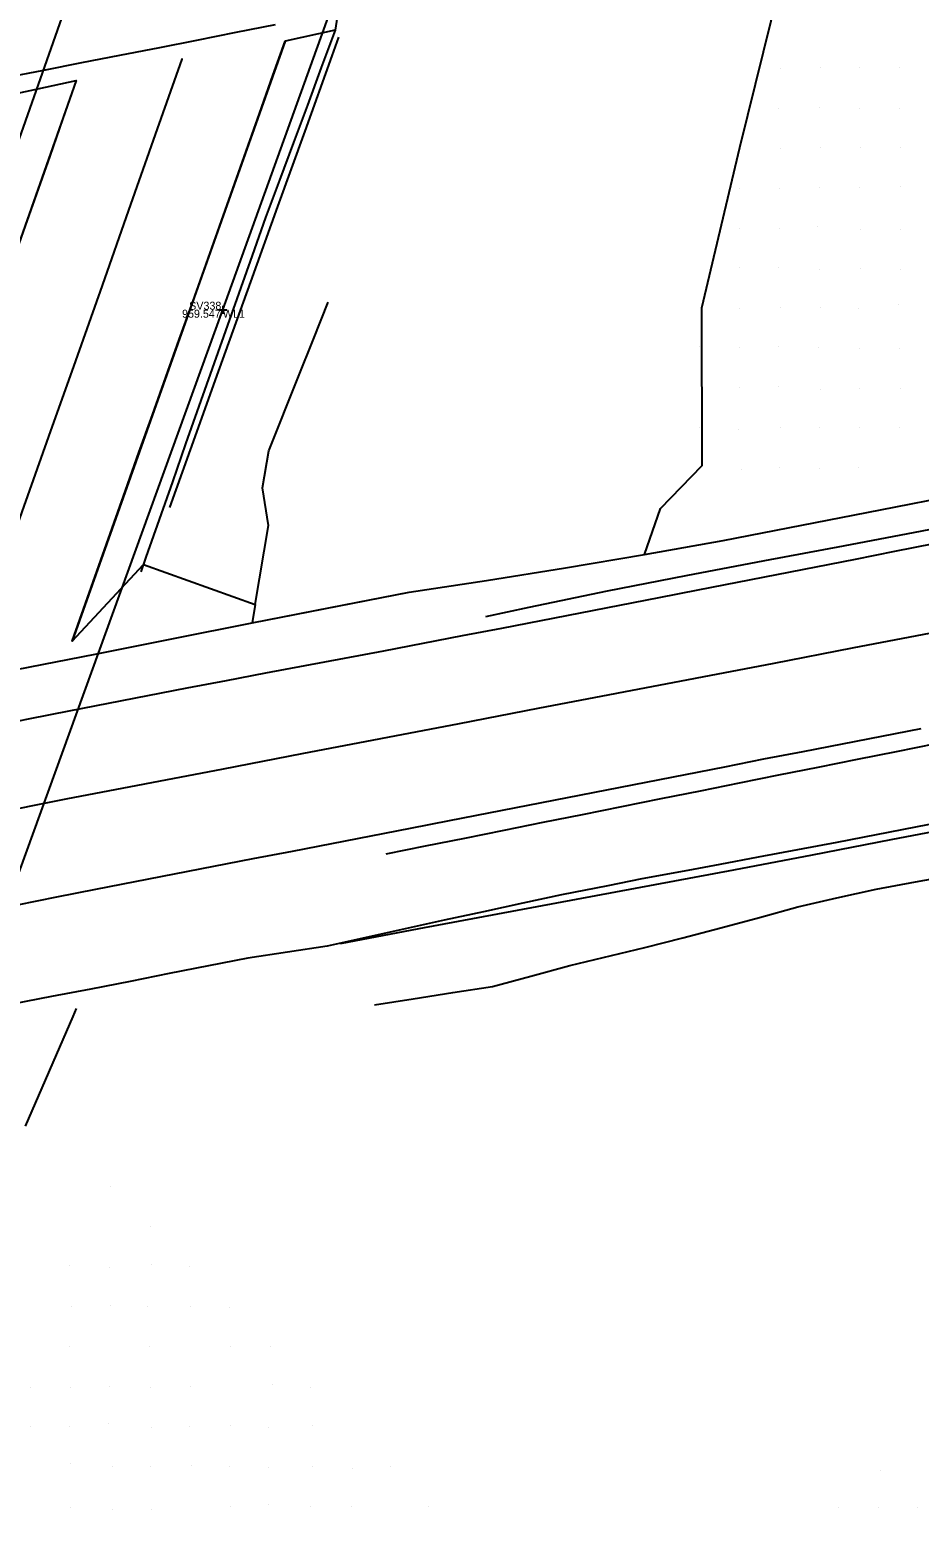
# Model space of a CAD drawing. Extents: x 2262025 to 2264532, y 740981 to 742724.
# Drawn here: x 2263228.5 to 2263339.6, y 741976.8 to 742163 of the extents above; entities that cross this region are included whole.
import ezdxf

# ---------------------------------------------------------------- set-up
doc = ezdxf.new("R2010")
doc.units = 0
for name, color, linetype in [('DT_X_Void', 7, 'Continuous'), ('GE_X_Alignment_1000_Curve_Data', 7, 'Continuous'), ('GE_X_Alignment_100_Bearings', 7, 'Continuous'), ('GE_X_Alignment_100_Curve_Data', 7, 'Continuous'), ('Ground Shots', 7, 'Continuous'), ('HY_X_Spring_Cells', 7, 'Continuous'), ('RW_X_CL', 7, 'Continuous'), ('RW_X_CL_1000_Distances', 7, 'Continuous'), ('RW_X_CL_100_Cardinal_Points', 7, 'Continuous'), ('SC_Scratch2', 7, 'Continuous'), ('SC_Scratch4', 7, 'Continuous'), ('SV_X_Control_Cells_Found', 7, 'Continuous'), ('SV_X_Text_Comment', 7, 'Continuous'), ('UT_X_Gas', 7, 'Continuous'), ('UT_X_Water', 7, 'Continuous')]:
    doc.layers.add(name, color=color, linetype=linetype)

msp = doc.modelspace()

# ---------------------------------------------------------------- linework, layer by layer
at = {"layer": 'DT_X_Void'}
for points in [[(2263307.26, 742103.15), (2263312.47, 742108.54), (2263312.43, 742128.22), (2263317.18, 742148.27), (2263322.09, 742168.18), (2263320.51, 742176.01), (2263266.96, 742165.11), (2263266.63, 742162.94), (2263260.36, 742161.57), (2263233.77, 742086.56), (2263242.67, 742096.15), (2263256.64, 742091.14), (2263256.25, 742088.84), (2263275.88, 742092.68), (2263285.52, 742094.16), (2263295.38, 742095.74), (2263305.24, 742097.38)], [(2263148.35, 742084.34), (2263148.83, 742139.39), (2263148.85, 742141.53), (2263177.37, 742146.41), (2263223.67, 742154.36), (2263228.51, 742155.39), (2263234.29, 742156.62), (2263207.86, 742081.52), (2263207.2, 742079.17), (2263202.2, 742080.57), (2263196.1, 742079.91), (2263195.53, 742076.88), (2263158.09, 742069.91), (2263148.41, 742067.47)]]:
    msp.add_lwpolyline(points, close=True, dxfattribs=at)
at = {"layer": 'GE_X_Alignment_1000_Curve_Data'}
for points in [[(2263457.67, 742123.27), (2263447.86, 742121.35), (2263438.05, 742119.42), (2263428.24, 742117.48), (2263418.43, 742115.54), (2263408.62, 742113.6), (2263398.81, 742111.66), (2263389, 742109.72), (2263379.19, 742107.78), (2263369.36, 742105.92), (2263359.54, 742104.05), (2263349.71, 742102.19), (2263339.89, 742100.32), (2263330.06, 742098.45), (2263320.24, 742096.59), (2263310.41, 742094.72), (2263300.59, 742092.83), (2263290.81, 742090.76), (2263285.41, 742089.61)], [(2263273.01, 742059.99), (2263277.92, 742060.98), (2263282.82, 742061.96), (2263287.72, 742062.95), (2263292.62, 742063.93), (2263297.52, 742064.92), (2263302.43, 742065.9), (2263307.33, 742066.89), (2263312.23, 742067.87), (2263317.13, 742068.85), (2263322.03, 742069.84), (2263326.94, 742070.82), (2263331.84, 742071.81), (2263336.74, 742072.79), (2263341.64, 742073.78)]]:
    msp.add_lwpolyline(points, dxfattribs=at)
at = {"layer": 'GE_X_Alignment_100_Bearings'}
for points in [[(2263245.96, 742103.26), (2263249.34, 742112.67), (2263251.69, 742119.21), (2263256.1, 742131.49), (2263259.48, 742140.9), (2263262.86, 742150.31), (2263266.25, 742159.72), (2263267.08, 742162.04)], [(2263267.27, 742048.8), (2263277.1, 742050.64), (2263286.93, 742052.48), (2263296.76, 742054.32), (2263306.59, 742056.16), (2263316.42, 742058), (2263326.24, 742059.88), (2263336.06, 742061.77), (2263345.88, 742063.65), (2263355.7, 742065.53), (2263365.53, 742067.41), (2263375.35, 742069.28), (2263385.15, 742071.27), (2263394.95, 742073.26), (2263404.75, 742075.25), (2263414.55, 742077.24), (2263424.35, 742079.24), (2263434.15, 742081.23), (2263440.14, 742082.45)]]:
    msp.add_lwpolyline(points, dxfattribs=at)
at = {"layer": 'GE_X_Alignment_100_Curve_Data'}
for points in [[(2263259.13, 742163.58), (2263254.22, 742162.62), (2263249.32, 742161.65), (2263244.69, 742160.74), (2263239.69, 742159.76), (2263234.95, 742158.83), (2263230.19, 742157.9), (2263225.42, 742156.96)], [(2263266.63, 742162.94), (2263264.89, 742158.25), (2263263.15, 742153.56), (2263261.41, 742148.87), (2263259.67, 742144.19), (2263257.94, 742139.5), (2263256.27, 742134.78), (2263254.59, 742130.07), (2263252.92, 742125.36), (2263251.24, 742120.65), (2263249.59, 742115.93), (2263247.94, 742111.21), (2263246.29, 742106.49), (2263244.64, 742101.77), (2263242.99, 742097.05), (2263242.35, 742095.24)], [(2263226.82, 742083.02), (2263236.63, 742084.96), (2263246.44, 742086.9), (2263256.25, 742088.84), (2263266.06, 742090.77), (2263275.88, 742092.68), (2263285.52, 742094.16), (2263295.38, 742095.74), (2263305.24, 742097.38), (2263315.09, 742099.14), (2263324.9, 742101.05), (2263334.71, 742102.97), (2263344.53, 742104.89), (2263354.34, 742106.8), (2263364.16, 742108.71), (2263373.98, 742110.61), (2263383.79, 742112.52), (2263393.61, 742114.42), (2263403.43, 742116.32), (2263413.25, 742118.21), (2263423.07, 742120.09), (2263432.89, 742121.98), (2263442.71, 742123.88), (2263452.52, 742125.82)], [(2263344, 742064.27), (2263339.09, 742063.31), (2263334.19, 742062.35), (2263329.28, 742061.42), (2263324.36, 742060.49), (2263319.45, 742059.56), (2263314.68, 742058.65), (2263310.66, 742057.91), (2263304.93, 742056.85), (2263300.68, 742056), (2263294.91, 742054.85), (2263290.08, 742053.81), (2263285.13, 742052.75), (2263280.25, 742051.69), (2263275.36, 742050.62), (2263270.49, 742049.52), (2263265.61, 742048.43), (2263260.66, 742047.69), (2263255.72, 742046.96), (2263250.82, 742045.99), (2263245.91, 742045.03), (2263241.01, 742044.05), (2263236.1, 742043.08), (2263231.19, 742042.14), (2263226.28, 742041.21)]]:
    msp.add_lwpolyline(points, dxfattribs=at)
at = {"layer": 'Ground Shots'}
for p, q in [((2263322.21, 742158.18), (2263322.21, 742158.18)), ((2263327.18, 742158.24), (2263327.18, 742158.24)), ((2263332.16, 742158.21), (2263332.16, 742158.21)), ((2263337.1, 742158.25), (2263337.1, 742158.25)), ((2263322.03, 742153.08), (2263322.03, 742153.08)), ((2263327.07, 742153.22), (2263327.07, 742153.22)), ((2263332.05, 742153.1), (2263332.05, 742153.1)), ((2263337.09, 742153.18), (2263337.09, 742153.18)), ((2263317.18, 742148.27), (2263317.18, 742148.27)), ((2263322.18, 742148.17), (2263322.18, 742148.17)), ((2263327.19, 742148.22), (2263327.19, 742148.22)), ((2263332.23, 742148.23), (2263332.23, 742148.23)), ((2263337.22, 742148.28), (2263337.22, 742148.28)), ((2263327.17, 742143.25), (2263327.17, 742143.25)), ((2263332.11, 742143.24), (2263332.11, 742143.24)), ((2263337.18, 742143.37), (2263337.18, 742143.37)), ((2263317.1, 742143.17), (2263317.1, 742143.17)), ((2263322.08, 742143.17), (2263322.08, 742143.17)), ((2263317.17, 742138.17), (2263317.17, 742138.17)), ((2263322.11, 742138.18), (2263322.11, 742138.18)), ((2263326.91, 742138.36), (2263326.91, 742138.36)), ((2263332.2, 742137.98), (2263332.2, 742137.98)), ((2263337.28, 742138.01), (2263337.28, 742138.01)), ((2263317.16, 742133.23), (2263317.16, 742133.23)), ((2263321.99, 742133.26), (2263321.99, 742133.26)), ((2263327.1, 742133.07), (2263327.1, 742133.07)), ((2263332.18, 742133.14), (2263332.18, 742133.14)), ((2263337.19, 742133.04), (2263337.19, 742133.04)), ((2263336.99, 742128.59), (2263336.99, 742128.59)), ((2263312.43, 742128.22), (2263312.43, 742128.22)), ((2263317.09, 742128.16), (2263317.09, 742128.16)), ((2263322.21, 742128.26), (2263322.21, 742128.26)), ((2263327.23, 742128.26), (2263327.23, 742128.26)), ((2263332.03, 742128.18), (2263332.03, 742128.18)), ((2263312.1, 742123.37), (2263312.1, 742123.37)), ((2263317.13, 742123.24), (2263317.13, 742123.24)), ((2263321.97, 742123.4), (2263321.97, 742123.4)), ((2263327, 742123.21), (2263327, 742123.21)), ((2263332.05, 742123.16), (2263332.05, 742123.16)), ((2263337.09, 742123.19), (2263337.09, 742123.19)), ((2263312.32, 742118.32), (2263312.32, 742118.32)), ((2263317.13, 742118.24), (2263317.13, 742118.24)), ((2263322.04, 742118.35), (2263322.04, 742118.35)), ((2263327.26, 742118.06), (2263327.26, 742118.06)), ((2263332.15, 742118.17), (2263332.15, 742118.17)), ((2263337.21, 742118.12), (2263337.21, 742118.12)), ((2263312.15, 742113.22), (2263312.15, 742113.22)), ((2263316.99, 742113.08), (2263316.99, 742113.08)), ((2263322.2, 742113.25), (2263322.2, 742113.25)), ((2263327.1, 742113.25), (2263327.1, 742113.25)), ((2263332.12, 742113.27), (2263332.12, 742113.27)), ((2263337.11, 742113.23), (2263337.11, 742113.23)), ((2263312.47, 742108.54), (2263312.47, 742108.54)), ((2263317.37, 742108.06), (2263317.37, 742108.06)), ((2263322.13, 742108.24), (2263322.13, 742108.24)), ((2263327.17, 742108.2), (2263327.17, 742108.2)), ((2263331.95, 742108.31), (2263331.95, 742108.31)), ((2263307.26, 742103.15), (2263307.26, 742103.15)), ((2263238.56, 742018.35), (2263238.56, 742018.35)), ((2263243.58, 742013.39), (2263243.58, 742013.39)), ((2263233.49, 742008.59), (2263233.49, 742008.59)), ((2263238.44, 742008.28), (2263238.44, 742008.28)), ((2263243.72, 742008.65), (2263243.72, 742008.65)), ((2263248.49, 742008.47), (2263248.49, 742008.47)), ((2263233.65, 742003.36), (2263233.65, 742003.36)), ((2263238.52, 742003.48), (2263238.52, 742003.48)), ((2263243.17, 742003.43), (2263243.17, 742003.43)), ((2263248.57, 742003.41), (2263248.57, 742003.41)), ((2263253.46, 742003.32), (2263253.46, 742003.32)), ((2263233.48, 741998.43), (2263233.48, 741998.43)), ((2263243.49, 741998.37), (2263243.49, 741998.37)), ((2263253.55, 741998.44), (2263253.55, 741998.44)), ((2263258.54, 741998.41), (2263258.54, 741998.41)), ((2263228.52, 741993.34), (2263228.52, 741993.34)), ((2263233.54, 741993.34), (2263233.54, 741993.34)), ((2263238.48, 741993.42), (2263238.48, 741993.42)), ((2263243.61, 741993.3), (2263243.61, 741993.3)), ((2263248.59, 741993.47), (2263248.59, 741993.47)), ((2263258.8, 741993.72), (2263258.8, 741993.72)), ((2263263.58, 741993.3), (2263263.58, 741993.3)), ((2263238.34, 741988.75), (2263238.34, 741988.75)), ((2263228.54, 741988.38), (2263228.54, 741988.38)), ((2263233.45, 741988.43), (2263233.45, 741988.43)), ((2263243.67, 741988.29), (2263243.67, 741988.29)), ((2263248.49, 741988.38), (2263248.49, 741988.38)), ((2263253.61, 741988.54), (2263253.61, 741988.54)), ((2263258.27, 741988.27), (2263258.27, 741988.27)), ((2263263.85, 741988.5), (2263263.85, 741988.5)), ((2263233.51, 741983.74), (2263233.51, 741983.74)), ((2263238.78, 741983.39), (2263238.78, 741983.39)), ((2263243.6, 741983.46), (2263243.6, 741983.46)), ((2263248.66, 741983.48), (2263248.66, 741983.48)), ((2263253.47, 741983.36), (2263253.47, 741983.36)), ((2263258.33, 741983.29), (2263258.33, 741983.29)), ((2263263.74, 741983.44), (2263263.74, 741983.44)), ((2263268.81, 741983.11), (2263268.81, 741983.11)), ((2263273.55, 741983.41), (2263273.55, 741983.41)), ((2263334.77, 741982.93), (2263334.77, 741982.93)), ((2263233.61, 741978.32), (2263233.61, 741978.32)), ((2263238.77, 741978.1), (2263238.77, 741978.1)), ((2263243.74, 741978.07), (2263243.74, 741978.07)), ((2263253.5, 741978.37), (2263253.5, 741978.37)), ((2263258.28, 741978.68), (2263258.28, 741978.68)), ((2263263.54, 741978.37), (2263263.54, 741978.37)), ((2263268.6, 741978.44), (2263268.6, 741978.44)), ((2263278.32, 741978.39), (2263278.32, 741978.39)), ((2263329.43, 741978.26), (2263329.43, 741978.26)), ((2263334.43, 741978.29), (2263334.43, 741978.29)), ((2263339.39, 741978.29), (2263339.39, 741978.29))]:
    msp.add_line(p, q, dxfattribs=at)
at = {"layer": 'RW_X_CL_1000_Distances'}
for points in [[(2263233.77, 742086.56), (2263235.44, 742091.27), (2263237.11, 742095.99), (2263238.77, 742100.7), (2263240.44, 742105.41), (2263242.11, 742110.13), (2263243.79, 742114.84), (2263245.47, 742119.55), (2263247.15, 742124.25), (2263248.83, 742128.96), (2263250.51, 742133.67), (2263252.18, 742138.39), (2263253.84, 742143.1), (2263255.5, 742147.82), (2263257.17, 742152.53), (2263258.83, 742157.25), (2263260.36, 742161.57)], [(2263234.29, 742156.62), (2263232.63, 742151.9), (2263230.97, 742147.18), (2263229.31, 742142.47), (2263227.65, 742137.75), (2263225.99, 742133.03), (2263224.33, 742128.32), (2263222.67, 742123.6), (2263221.01, 742118.88), (2263219.35, 742114.17), (2263217.69, 742109.45), (2263216.03, 742104.74), (2263214.37, 742100.02), (2263212.71, 742095.3), (2263211.05, 742090.59), (2263209.39, 742085.87), (2263207.86, 742081.52)], [(2263223.61, 742075.91), (2263228.51, 742076.88), (2263233.42, 742077.84), (2263238.32, 742078.8), (2263243.23, 742079.77), (2263248.14, 742080.73), (2263253.05, 742081.66), (2263257.96, 742082.59), (2263262.88, 742083.51), (2263267.79, 742084.43), (2263272.7, 742085.37), (2263277.61, 742086.31), (2263282.52, 742087.26), (2263287.43, 742088.21), (2263292.34, 742089.16), (2263297.25, 742090.11), (2263302.16, 742091.06), (2263307.07, 742092.01), (2263311.97, 742092.97), (2263316.88, 742093.92), (2263321.79, 742094.89), (2263326.69, 742095.86), (2263331.6, 742096.83), (2263336.5, 742097.8), (2263341.41, 742098.77)], [(2263226.94, 742053.63), (2263231.84, 742054.6), (2263236.74, 742055.57), (2263241.65, 742056.54), (2263246.56, 742057.49), (2263251.47, 742058.44), (2263256.38, 742059.39), (2263261.29, 742060.34), (2263266.19, 742061.29), (2263271.1, 742062.24), (2263276.01, 742063.19), (2263280.92, 742064.14), (2263285.83, 742065.1), (2263290.73, 742066.06), (2263295.64, 742067.02), (2263300.55, 742067.99), (2263305.45, 742068.95), (2263310.36, 742069.92), (2263315.27, 742070.88), (2263320.17, 742071.84), (2263325.08, 742072.79), (2263329.99, 742073.74), (2263334.9, 742074.69), (2263339.81, 742075.64)]]:
    msp.add_lwpolyline(points, dxfattribs=at)
at = {"layer": 'RW_X_CL_100_Cardinal_Points'}
for p, q in [((2263252.6, 742128.49), (2263252.6, 742127.49)), ((2263252.1, 742127.99), (2263253.1, 742127.99)), ((2263252.6, 742127.99), (2263252.6, 742127.99))]:
    msp.add_line(p, q, dxfattribs=at)
at = {"layer": 'SC_Scratch2'}
msp.add_lwpolyline([(2263223.23, 742064.92), (2263233.04, 742066.86), (2263242.86, 742068.75), (2263252.69, 742070.63), (2263262.51, 742072.52), (2263272.33, 742074.4), (2263282.15, 742076.29), (2263291.97, 742078.18), (2263301.79, 742080.06), (2263311.61, 742081.95), (2263321.43, 742083.83), (2263331.25, 742085.72), (2263341.07, 742087.6)], dxfattribs=at)
at = {"layer": 'SC_Scratch4'}
msp.add_lwpolyline([(2263220.84, 742083.89), (2263224.19, 742093.32), (2263227.53, 742102.74), (2263230.88, 742112.16), (2263234.23, 742121.59), (2263237.55, 742131.02), (2263240.87, 742140.45), (2263244.18, 742149.89), (2263247.5, 742159.32), (2263247.51, 742159.37)], dxfattribs=at)
at = {"layer": 'SV_X_Control_Cells_Found'}
for points in [[(2263256.64, 742091.14), (2263258.29, 742101.01), (2263257.54, 742105.75), (2263258.35, 742110.37), (2263262.06, 742119.66), (2263263.91, 742124.3), (2263265.76, 742128.95)], [(2263271.53, 742041.1), (2263276.38, 742041.86), (2263281.32, 742042.64), (2263286.26, 742043.41), (2263291.08, 742044.71), (2263295.91, 742046.02), (2263305.31, 742048.27), (2263310.05, 742049.49), (2263314.8, 742050.73), (2263319.61, 742052.04), (2263324.42, 742053.36), (2263329.29, 742054.48), (2263334.17, 742055.58), (2263339.09, 742056.48), (2263344.01, 742057.35)], [(2263227.94, 742025.95), (2263233.88, 742039.67), (2263234.31, 742040.66)]]:
    msp.add_lwpolyline(points, dxfattribs=at)
at = {"layer": 'UT_X_Gas'}
msp.add_lwpolyline([(2263370.65, 742558.56), (2263358.32, 742523.53), (2263332.75, 742449.83), (2263131.85, 741878.34), (2263108.26, 741811.62)], dxfattribs=at)
at = {"layer": 'UT_X_Water'}
msp.add_lwpolyline([(2263058.18, 741572.97), (2263085.82, 741651.25), (2263095.93, 741679.99), (2263097.95, 741685.82), (2263106.82, 741712.78), (2263147.36, 741828.66), (2263178.07, 741920.18), (2263217.98, 742032.49), (2263252.6, 742127.99), (2263295.63, 742247.6), (2263334.95, 742356.22), (2263370.78, 742449.55), (2263413.67, 742573.04), (2263421.38, 742593.43)], dxfattribs=at)

# ---------------------------------------------------------------- texts
at = {"layer": 'HY_X_Spring_Cells'}
msp.add_text('959.547', height=1, dxfattribs=at).set_placement((2263247.5, 742126.99))
at = {"layer": 'RW_X_CL'}
msp.add_text('WL1', height=1, dxfattribs=at).set_placement((2263252.6, 742126.99))
at = {"layer": 'SV_X_Text_Comment'}
msp.add_text('SV338', height=1, dxfattribs=at).set_placement((2263248.39, 742127.99))

doc.saveas('drawing.dxf')
